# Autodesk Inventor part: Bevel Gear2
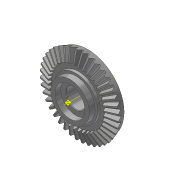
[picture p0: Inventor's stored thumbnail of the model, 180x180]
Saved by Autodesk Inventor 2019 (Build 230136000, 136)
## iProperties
Created: 2019-01
Part Number: Bevel Gear2
Material: Steel, Mild
Document SubType Name: Modeling
Designer: m.vorobev
Categories: <?xml version="1.0" encoding="UTF-16"?> <MemberInstance><Categories><FamilyTemplate><FamilyTemplateParameter ValueType="xs:double" Id="1" ObjectReferenceKey="da
Mass: 60.9118 g
Surface Area: 34.3074 cm^2
Volume: 7.7496 cm^3
Density: 7.86 g/cm^3
Appearance: Steel
CustomPartVersion: 1
Author: m.vorobev
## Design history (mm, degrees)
node "Top Point"
node "Mesh Plane2"
sketch "Teeth Body Sketch"
  geometry: L1 (0, 0)-(78.414, -32.531); L2 (78.414, -32.531)-(81.321, -24.225); L3 (81.321, -24.225)-(0, 0); L4 (80, -28)-(0, 0); L5 (55.286, -22.935)-(57.335, -17.079); L6 (78.414, -32.531)-(55.286, -22.935); L7 (81.321, -24.225)-(57.335, -17.079); L8 (0, -39.387)-(0, 6.564) reference; L9 (0, -28)-(81.321, -28)
  constraints: 16 end point, 4 point on line, 3 perpendicular, 2 collinear, 1 horizontal alignment, 1 vertical alignment
  dimensions: "d0" = 160 diameter of L4.start L8 (= da_de); "d1" = 156.82864 diameter of L1.end L8 (= da_dfe); "d2" = 162.6428 diameter of L2.end L8 (= da_dae); "d3" = 25 distance between parallel lines of L2 L5 (= da_b); "d4" = 24.22457 vertical distance of L2.end L1.start (= da_ve)
revolve "Teeth Body" sketch "Teeth Body Sketch" stored, may be unused: angle "d5" = 90 deg
node "Start Point"
node "Tooth Plane"
sketch "Start Sketch"
  geometry: L1 (0, -23.505)-(0, 10.645) reference; L2 (-1.283, -5.856)-(1.283, -5.856); A1 r 84.219 centre (-82.286, -28.909) between (-1.283, -5.856) and (-5.905, 6.57); A2 r 84.219 centre (82.286, -28.909) between (5.905, 6.57) and (1.283, -5.856); A3 r 248.807 centre (0, -242.167) between (5.905, 6.57) and (-5.905, 6.57); 1 further point
  constraints: 6 point on circle, 3 centre point, 3 symmetric about line, 2 end point, 1 coincident, 1 perpendicular, 1 other
  dimensions: "d7" = 84.21912 radius of A1 (= fd_rr); "d8" = 82.28596 horizontal distance of point (0, -242.167) A1.centre (= fd_x); "d9" = 213.25785 vertical distance of point (0, -242.167) A1.centre (= fd_y); "d57" = 248.80709 radius of A3 (= 0.5 x fd_dva + 0.3 x da_he); "d58" = 236.31109 distance from line of A3.centre L2 (= 0.5 x fd_dva - 1.12 x da_he)
node "End Point"
  node "End Plane"
sketch "3D Sketch Right"
  node "Helical Curve Right" dims "d65" = 388.94171 (computed from da_dm, da_delta, da_beta), "d66" = 31.5, "d67" = 160 (= da_de), "d68" = -12.34122 (= -da_delta), "d69" = 8.40411 (computed from fd_loft, da_delta)
node "End Plane Right"
sketch "End Sketch Right"
  geometry: L1 (0, -204.954)-(0, 39.264) reference; L2 (-0.899, -3.862)-(0.899, -3.862); A1 r 59.025 centre (-57.67, -20.019) between (-0.899, -3.862) and (-4.138, 4.847); A2 r 59.025 centre (57.67, -20.019) between (4.138, 4.847) and (0.899, -3.862); A3 r 174.377 centre (0, -169.481) between (4.138, 4.847) and (-4.138, 4.847); 1 further point
  constraints: 6 point on circle, 3 centre point, 3 symmetric about line, 2 end point, 1 coincident, 1 perpendicular, 1 other
  dimensions: "d70" = 57.67036 horizontal distance of A3.centre A1.centre (computed from fd_x, fd_ratio); "d71" = 149.46241 vertical distance of point (0, -169.481) A1.centre (computed from fd_y, fd_ratio); "d72" = 59.02523 radius of A1 (computed from fd_rr, fd_ratio); "d73" = 165.61934 distance from line of point (0, -169.481) L2 (computed from d58, fd_ratio); "d74" = 174.3772 radius of A3 (computed from d57, fd_ratio)
feature "Loft Right" sketch "End Sketch Right" dims "d75" = 0, "d77" = 0, "d79" = 0, "d80" = 90 deg, "d85" = 20, "d92" = 90 deg, "d93" = 90 deg, "da_teethtype" = 0 [user parameter]
sketch "3D Sketch Left"
  node "Helical Curve Left" dims "d26" = 388.94171 (computed from da_dm, da_delta, da_beta), "d27" = 8.40411 (computed from fd_loft, da_delta), "d28" = 160 (= da_de), "d29" = -12.34122 (= -da_delta)
node "End Plane Left"
sketch "End Sketch Left" dims "d56" = 19.01874 (derived)
  geometry: L1 (0, -205.693)-(0, 40.091) reference; L2 (-0.899, -3.776)-(0.899, -3.776); A1 r 59.025 centre (-57.67, -19.933) between (-0.899, -3.776) and (-4.138, 4.932); A2 r 59.025 centre (57.67, -19.933) between (4.138, 4.932) and (0.899, -3.776); A3 r 174.377 centre (0, -169.396) between (4.138, 4.932) and (-4.138, 4.932); 2 further points; 1 other entity
  constraints: 6 point on circle, 3 centre point, 3 symmetric about line, 2 end point, 1 coincident, 2 other
  dimensions: "d30" = 59.02523 radius of A1 (computed from fd_rr, fd_ratio); "d31" = 57.67036 horizontal distance of point (0, -169.396) A1.centre (computed from fd_x, fd_ratio); "d32" = 149.46241 vertical distance of A1.centre point (0, -169.396) (computed from fd_y, fd_ratio); "d61" = 174.3772 radius of A3 (computed from d57, fd_ratio); "d62" = 165.61934 distance from line of point (0, -169.396) L2 (computed from d58, fd_ratio)
feature "Loft Left" sketch "End Sketch Left" dims "d35" = 0, "d37" = 0, "d39" = 0, "d40" = 90 deg, "d84" = 10, "d90" = 90 deg, "d91" = 90 deg, "da_teethtype" = 0 [user parameter]
sketch "Body Sketch"
  geometry: L1 (0, -35.038)-(0, -19.531) reference; L2 (78.414, -32.531)-(55.286, -22.935) reference; L3 (55.286, -22.935)-(0, -22.935); L4 (78.414, -32.531)-(0, -32.531)
  constraints: 4 end point, 2 perpendicular, 2 point on line
revolve "Fix Body" sketch "Body Sketch" stored, may be unused: angle "d46" = 90 deg
sketch "Sketch6"
  geometry: L1 (80, -28)-(0, 0) reference; L2 (0, -37.8)-(0, 6.3) reference
feature "Pitch Diameter" sketch "Sketch6" dims angle "d47" = 90 deg
sketch "Sketch8"
  geometry: L1 (55.286, -22.935)-(57.335, -17.079) reference; L2 (81.321, -24.225)-(57.335, -17.079) reference; L3 (78.414, -32.531)-(81.321, -24.225) reference; L4 (78.414, -32.531)-(55.286, -22.935) reference; L5 (78.414, -32.531)-(75.072, -42.079); L6 (75.072, -42.079)-(55.286, -42.079); L7 (55.286, -42.079)-(55.286, -22.935); L8 (78.414, -32.531)-(55.286, -22.935); L9 (77.682, -32.531)-(78.398, -32.531) reference; L10 (78.398, -32.531)-(79.868, -32.531); L11 (79.868, -32.531)-(79.868, -37.903); L12 (79.868, -37.903)-(78.398, -37.903); L13 (78.398, -37.903)-(78.398, -32.531); L14 (55.286, -42.079)-(20, -42.079); L15 (20, -42.079)-(20, -22.935); L16 (20, -22.935)-(55.286, -22.935); L17 (55.286, -22.935)-(55.286, -42.079); L18 (20, -22.935)-(45, -22.935); L19 (45, -22.935)-(45, -17.079); L20 (45, -17.079)-(20, -17.079); L21 (20, -17.079)-(20, -22.935); L22 (31, -17.079)-(40, -17.079); L23 (40, -17.079)-(40, -5.079); L24 (40, -5.079)-(31, -5.079); L25 (31, -5.079)-(31, -17.079); L26 (0, -50.495)-(0, 8.416) reference; 2 further points
  constraints: 40 end point, 9 equal length, 5 horizontal, 4 perpendicular, 1 collinear, 1 point on line, 1 vertical
  dimensions: "d95" = 25 distance from line of L1.end L6; "d96" = 19.29 deg angle of L5 L13 (derived); "d97" = 40 diameter of L21 L26; "d98" = 62 diameter of L25 L26; "d99" = 12 distance of L24.end L22.start; "d100" = 25 distance between parallel lines of L14 L22; "d101" = 90 diameter of L19 L26; "d102" = 80 diameter of L23 L26; "d103" = 37 distance between parallel lines of L14 L24 (derived)
revolve "Revolution3" sketch "Sketch8" stored, may be unused: angle "d104" = 90 deg
delete_face "Delete Face1"
chamfer "Chamfer1" distance "d105" = 1; stored, may be unused: second distance "d106" = 2, angle "d107" = 45 deg
body "Solid1"
feature "Loft" dims "d17" = 0, "d18" = 90 deg, "d19" = 0, "d20" = 90 deg, "d89" = 0, "da_teethtype" = 0 [user parameter]
pattern_circular "Circular Pattern" dims angle "d22" = 360 deg, "d88" = 0, "da_teethtype" = 0 [user parameter]
pattern_circular "Circular Pattern Right" dims angle "d82" = 360 deg, "da_teethtype" = 0 [user parameter]
pattern_circular "Circular Pattern Left" dims angle "d42" = 360 deg, "da_teethtype" = 0 [user parameter]
sketch "End Sketch"
  geometry: L1 (0, -15.359)-(0, 6.983) reference; L2 (-0.899, -3.862)-(0.899, -3.862); A1 r 59.025 centre (-57.67, -20.019) between (-0.899, -3.862) and (-4.138, 4.847); A2 r 59.025 centre (57.67, -20.019) between (4.138, 4.847) and (0.899, -3.862); A3 r 174.377 centre (0, -169.481) between (4.138, 4.847) and (-4.138, 4.847); 1 further point
  constraints: 6 point on circle, 3 centre point, 3 symmetric about line, 2 end point, 1 coincident, 1 other
  dimensions: "d12" = 59.02523 radius of A1 (computed from fd_rr, fd_ratio); "d15" = 57.67036 horizontal distance of A1.centre point (0, -169.481) (computed from fd_x, fd_ratio); "d16" = 149.46241 vertical distance of A1.centre point (0, -169.481) (computed from fd_y, fd_ratio); "d59" = 174.3772 radius of A3 (computed from d57, fd_ratio); "d60" = 165.61934 distance from line of A3.centre L2 (computed from d58, fd_ratio)
body "Srf1"
other parameters: "da_b" = 25 [user parameter; used in 2 equation terms], "da_de" = 160 [user parameter; used in 4 equation terms], "da_dae" = 162.6428 [user parameter; used in 2 equation terms], "da_dfe" = 156.82864 [user parameter; used in 1 equation term], "da_le" = 84.75848 [user parameter; used in 1 equation term], "da_omega" = 90 deg [user parameter; used in 1 equation term], "da_beta" = 0 [user parameter; used in 2 equation terms], "da_delta" = 12.34122 [user parameter; used in 8 equation terms], "da_alpha" = 20 deg [user parameter; used in 2 equation terms], "da_he" = 8.8 [user parameter; used in 4 equation terms], "da_ve" = 24.22457 [user parameter; used in 1 equation term], "fd_dv" = 484.33417 (computed from da_de, da_delta) [user parameter; used in 1 equation term], "fd_dva" = 492.33417 (computed from da_dae, da_delta) [user parameter; used in 3 equation terms], "fd_dvb" = 455.12525 (computed from fd_dv, da_alpha) [user parameter; used in 2 equation terms], "da_zv" = 1210.83543 [user parameter; used in 1 equation term], "fd_loft" = 25.44 (= da_b + 0.05 x da_he) [user parameter; used in 4 equation terms], "fd_ratio" = 7.00853 (computed from da_le, fd_loft) [user parameter; used in 15 equation terms], "fd_rr" = 84.21912 (computed from fd_dd, fd_dvb) [user parameter; used in 6 equation terms], "fd_angle" = 0.13117 (computed from da_zv) [user parameter; used in 4 equation terms], "fd_x1" = 3.17641 (computed from da_dvw, fd_angle) [user parameter; used in 1 equation term], "fd_y1" = 242.14625 (computed from da_dvw, fd_angle) [user parameter; used in 1 equation term], "fd_x2" = 79.10955 (computed from fd_rr, fd_angle2, fd_angle) [user parameter; used in 1 equation term], "fd_y2" = 28.88841 (computed from fd_rr, fd_angle2, fd_angle) [user parameter; used in 1 equation term], "fd_x" = 82.28596 (= fd_x1 + fd_x2) [user parameter; used in 4 equation terms], "fd_y" = 213.25785 (= fd_y1 - fd_y2) [user parameter; used in 4 equation terms], "fd_angle2" = 3.37008 (computed from fd_dvb, fd_dd, da_alpha) [user parameter; used in 2 equation terms], "fd_dd" = 485.29417 (= fd_dva - 0.8 x da_he) [user parameter; used in 2 equation terms], "da_dvw" = 484.33417 [user parameter; used in 2 equation terms], "d11" = 25.44 (= fd_loft), "da_dm" = 136.40354 [user parameter; used in 2 equation terms], "da_x" = 0 [user parameter], "da_m" = 4 [user parameter], "d48" = 0, "d49" = 0, "d50" = 90 deg (= da_omega), "d51" = 4.5 deg (computed from da_z), "d52" = 0, "d53" = 0, "d54" = 0
